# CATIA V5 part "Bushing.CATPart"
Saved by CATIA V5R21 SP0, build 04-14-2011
Part number: Bushing
Bounding box of the stored display mesh (mm): x -13.45 to 13.45, y 0 to 63, z -13.45 to 13.45
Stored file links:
  D:\CATIA V5R21 E-RESOURCES\CATIA-V5R21\catia-v5r21-Prts\c12_catia_v5r21_prt\c12_catia_v5r21figr_12-54 to 56\Bushing.CATPart
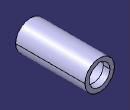
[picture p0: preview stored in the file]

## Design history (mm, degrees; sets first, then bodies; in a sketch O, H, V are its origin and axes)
Body1 (main body)
  Sketch1 on zx-plane, origin (0, 0, 0), H (-1, 0, 0), V (0, 0, 1)
    circle A1 centre (0, 0) radius 9.5
    circle A2 centre (0, 0) radius 13.45
    radius A1 = 9.5
    radius A2 = 13.45
  Pad1: profile Sketch1, direction (0, 1, 0), length 63
  Sketch2 on face of Pad1, origin (0, 63, 0), H (-1, 0, 0), V (0, 0, 1)
    line L1 (-1.5, 9.3808) -> (1.5, 9.3808)
    line L2 (1.5, 9.3808) -> (1.5, 10.1808)
    line L3 (1.5, 10.1808) -> (-1.5, 10.1808)
    line L4 (-1.5, 10.1808) -> (-1.5, 9.3808)
    point P2 (1.5, 9.3808)
    reference projected circle E1 centre (0, 0) radius 9.5 from edge of Pad1
    length L3 = 3
    length L2 = 0.8
    distance V L4 = 1.5
    horizontal: L1 H, L3 H
    vertical: L2 V, L4 V
    coincidence: P2 E1
  Pocket1: profile Sketch2, direction (0, -1, 0), through (limit type 6)
  Sketch3 on xy-plane, origin (0, 0, 0), H (1, 0, 0), V (0, 1, 0)
    line L1 (9.5, 57) -> (10.3, 57)
    line L2 (10.3, 57) -> (10.3, 49)
    line L3 (10.3, 49) -> (9.5, 49)
    line L4 (9.5, 49) -> (9.5, 57)
    reference projected line E1 (13.45, 63) -> (-13.45, 63) from edge of Pad1
    length L2 = 8
    length L1 = 0.8
    distance L3 E1 = 14
    distance V L4 = 9.5
    horizontal: L1 H, L3 H
    vertical: L2 V, L4 V
  Groove1: profile Sketch3, axis axis of face of Pad1, angle 360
